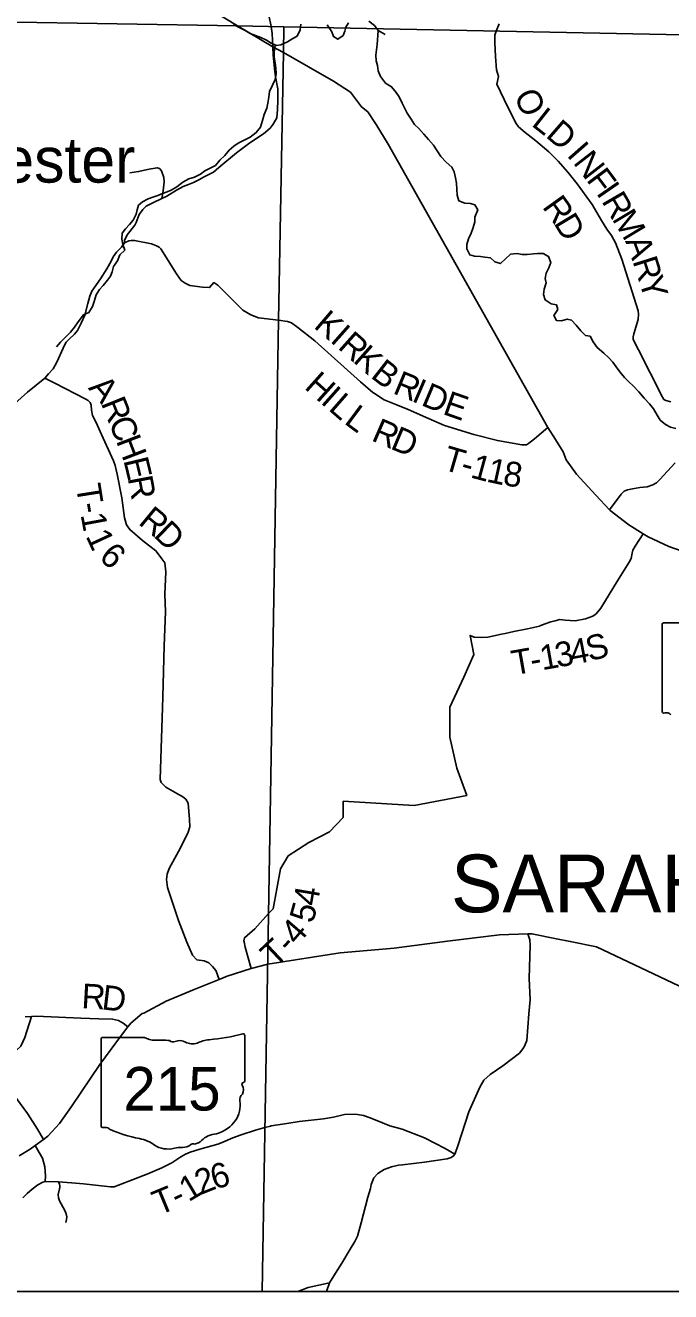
# Model space of a CAD drawing. Extents: x -22 to 431, y -18 to 160.
# Drawn here: x -5.357 to -3.877, y 14.134 to 17.042 of the extents above; entities that cross this region are included whole.
import ezdxf

# ---------------------------------------------------------------- set-up
doc = ezdxf.new("R2010")
doc.units = 0
for name, color, linetype in [('GM_X_Adjacent_County', 7, 'Continuous'), ('GM_X_Adjacent_County_Text', 7, 'Continuous'), ('GM_X_Airport_Location_Class_2', 7, 'Continuous'), ('GM_X_City_Street', 7, 'Continuous'), ('GM_X_City_Street_Text', 7, 'Continuous'), ('GM_X_County_Road', 7, 'Continuous'), ('GM_X_Interstate_Location', 7, 'Continuous'), ('GM_X_Major_River_Text', 7, 'Continuous'), ('GM_X_Minor_River', 7, 'Continuous'), ('GM_X_Minor_River_Text', 7, 'Continuous'), ('GM_X_Rail_Line', 7, 'Continuous'), ('GM_X_Section', 7, 'Continuous')]:
    doc.layers.add(name, color=color, linetype=linetype)

msp = doc.modelspace()

# ---------------------------------------------------------------- linework, layer by layer
at = {"layer": 'GM_X_Adjacent_County_Text'}
for points in [[(-4.7893, 16.9922), (-4.7907, 17.0228), (-4.7931, 17.0387), (-4.7988, 17.0653), (-4.8017, 17.0921), (-4.7983, 17.1237), (-4.7945, 17.1452), (-4.7979, 17.1548)], [(-4.2702, 17.0448), (-4.2773, 17.0283), (-4.2805, 17.0191), (-4.2805, 17.016)], [(-4.2805, 17.016), (-4.2802, 17.0019), (-4.2788, 16.97), (-4.2762, 16.9395), (-4.2721, 16.9238), (-4.276, 16.9062), (-4.2502, 16.854), (-4.2314, 16.8166), (-4.2256, 16.8083), (-4.2103, 16.7955), (-4.1863, 16.7763), (-4.1562, 16.7511), (-4.1351, 16.73), (-4.1126, 16.7043), (-4.0911, 16.6779), (-4.0566, 16.6303), (-4.0355, 16.5933), (-4.0232, 16.5736), (-4.0125, 16.5589), (-4.0033, 16.5422), (-3.989, 16.5051), (-3.9517, 16.3862), (-3.9505, 16.3782), (-3.9512, 16.3665), (-3.9612, 16.3334), (-3.963, 16.3262), (-3.963, 16.3205), (-3.951, 16.2966), (-3.8963, 16.1894)], [(-4.7853, 16.9424), (-4.789, 16.9728), (-4.7893, 16.9922)], [(-5.3813, 16.1734), (-5.3521, 16.1996), (-5.3128, 16.2319), (-5.3037, 16.2414), (-5.2935, 16.2528), (-5.2848, 16.268), (-5.2708, 16.3003), (-5.2667, 16.3086), (-5.2633, 16.3139), (-5.2568, 16.3215), (-5.2447, 16.3329), (-5.2375, 16.3413), (-5.2288, 16.3576), (-5.2205, 16.3762), (-5.2141, 16.4032), (-5.2096, 16.4195), (-5.2047, 16.4312), (-5.185, 16.4593), (-5.1706, 16.4825), (-5.1604, 16.5003), (-5.1555, 16.5102), (-5.1479, 16.5205), (-5.1366, 16.5326), (-5.1298, 16.5425), (-5.1294, 16.5478), (-5.1238, 16.5603), (-5.1064, 16.5827), (-5.1029, 16.5892), (-5.0958, 16.607), (-5.0874, 16.6188), (-5.0803, 16.6268), (-5.0644, 16.634), (-5.0439, 16.6443), (-5.0329, 16.6492), (-5.0106, 16.6629), (-4.9951, 16.6713), (-4.9826, 16.6766), (-4.9713, 16.6808), (-4.9576, 16.688), (-4.9489, 16.6933), (-4.9349, 16.6998), (-4.9258, 16.7044), (-4.9137, 16.715), (-4.8729, 16.7492), (-4.8422, 16.772), (-4.8112, 16.7929), (-4.7957, 16.8054), (-4.7888, 16.8145), (-4.7806, 16.8291), (-4.7787, 16.8482), (-4.7778, 16.8693), (-4.7778, 16.8961), (-4.783, 16.9233), (-4.7853, 16.9424)], [(-3.8963, 16.1894), (-3.8961, 16.1889), (-3.8956, 16.1881), (-3.8922, 16.1828), (-3.888, 16.1801), (-3.8762, 16.1772)], [(-3.8664, 16.0371), (-3.9018, 15.9989), (-3.9097, 15.9913), (-3.9177, 15.9867), (-3.9305, 15.9824), (-3.948, 15.9804), (-3.9642, 15.9776), (-3.9756, 15.9749), (-3.9832, 15.9725), (-3.9907, 15.9656), (-4.017, 15.9293)], [(-5.2301, 14.7627), (-5.3326, 14.7671), (-5.3432, 14.766), (-5.3576, 14.7652)], [(-5.1219, 14.7422), (-5.1326, 14.7507), (-5.1432, 14.7568), (-5.1576, 14.7598), (-5.1887, 14.7609), (-5.2301, 14.7627), (-5.2301, 14.7627)]]:
    msp.add_lwpolyline(points, dxfattribs=at)
at = {"layer": 'GM_X_Airport_Location_Class_2'}
for p, q in [((-3.8933, 15.6699), (-3.7968, 15.6699)), ((-3.8965, 15.6665), (-3.8965, 15.4664)), ((-3.8965, 15.4664), (-3.8965, 15.6665)), ((-3.8965, 15.4664), (-3.8965, 15.6665)), ((-5.1836, 14.7147), (-5.1836, 14.5146)), ((-5.1836, 14.5146), (-5.1836, 14.7147)), ((-5.1836, 14.5146), (-5.1836, 14.7147)), ((-5.1803, 14.7181), (-5.0838, 14.7181)), ((-4.854, 14.7231), (-4.854, 14.6184)), ((-4.854, 14.6184), (-4.854, 14.6184))]:
    msp.add_line(p, q, dxfattribs=at)
for centre, major_axis, start_param, end_param in [((-3.8928, 15.6669), (0.00382, 0), 1.712693, 3.28349), ((-3.8927, 15.4659), (0.00385, 0), 3.00124, 4.508301), ((-3.8921, 15.4864), (0.0294, 0), 4.665946, 4.897461), ((-3.8861, 15.4548), (0.0106, 0), 0.519207, 1.627899), ((-5.1798, 14.7151), (0.00382, 0), 1.712693, 3.28349), ((-5.0608, 14.7414), (0.037, 0), 4.042523, 4.731795), ((-5.0485, 14.6058), (0.133, 0), 1.404758, 1.657858), ((-5.0183, 14.7162), (0.0107, 0), 3.836095, 5.185415), ((-5.0027, 14.693), (0.0222, 0), 0.950623, 2.079405), ((-4.9268, 14.657), (0.0703, 0), 1.699011, 2.107814), ((-4.9714, 14.991), (0.3495, 0), 4.814394, 5.042369), ((-4.8576, 14.7235), (0.00367, 0), 6.141152, 7.989035), ((-4.974, 14.7247), (0.0267, 0), 4.081561, 5.145723), ((-4.8548, 14.6107), (0.00568, 0), 1.883978, 3.671073), ((-4.8909, 14.5975), (0.0341, 0), 5.934695, 6.695948), ((-4.8579, 14.618), (0.00393, 0), 5.05454, 6.418171), ((-4.9518, 14.5613), (0.0874, 0), 5.101752, 6.440018), ((-4.8408, 14.5746), (0.0248, 0), 2.387724, 3.262537), ((-5.1797, 14.5141), (0.00385, 0), 3.00124, 4.508301), ((-5.1792, 14.5346), (0.0294, 0), 4.665946, 4.897461), ((-5.1731, 14.503), (0.0106, 0), 0.519207, 1.627899), ((-5.0393, 14.6828), (0.2524, 0), 4.195997, 4.488961), ((-5.1146, 14.4247), (0.079, 0), 0.823519, 1.323587), ((-4.9756, 14.4952), (0.0282, 0), 4.937069, 5.64225), ((-4.9149, 14.4584), (0.0479, 0), 1.647645, 2.488434), ((-5.0292, 14.502), (0.0501, 0), 4.026481, 4.996735), ((-5.0002, 14.4328), (0.0412, 0), 1.495662, 1.94098), ((-4.9965, 14.487), (0.0267, 0), 4.691044, 5.507374), ((-4.9724, 14.4677), (0.00752, 0), 1.147584, 2.315152)]:
    msp.add_ellipse(centre, major_axis=major_axis, ratio=0.8, start_param=start_param, end_param=end_param, dxfattribs=at)
at = {"layer": 'GM_X_County_Road'}
for points in [[(-5.0416, 15.8138), (-5.0372, 15.8075), (-5.0351, 15.787), (-5.037, 15.7361), (-5.036, 15.6951), (-5.0388, 15.6169), (-5.0417, 15.4989), (-5.0476, 15.3105), (-5.0456, 15.3033), (-5.035, 15.2928), (-5.0027, 15.2745), (-5, 15.273), (-4.9963, 15.2703)], [(-4.6283, 15.2606), (-4.4656, 15.2508), (-4.3446, 15.2737), (-4.3675, 15.3359), (-4.3838, 15.4078), (-4.3838, 15.4765), (-4.3511, 15.5452), (-4.3282, 15.5976), (-4.3369, 15.6412), (-4.3278, 15.6374), (-4.3111, 15.6364), (-4.2963, 15.6373), (-4.2653, 15.6436), (-4.2562, 15.6456)], [(-5.3156, 14.4841), (-5.3295, 14.5079), (-5.3525, 14.5438), (-5.3693, 14.5668), (-5.385, 14.5887), (-5.3954, 14.6099), (-5.4035, 14.6246), (-5.408, 14.6325), (-5.413, 14.639), (-5.4225, 14.6438), (-5.4491, 14.6535), (-5.3778, 14.6886), (-5.3676, 14.6981), (-5.3587, 14.7179), (-5.3432, 14.766)], [(-4.3719, 14.4505), (-4.3938, 14.4631), (-4.4418, 14.4878), (-4.4928, 14.5072), (-4.5209, 14.5154), (-4.5379, 14.5221), (-4.566, 14.5332), (-4.5812, 14.5388), (-4.6002, 14.5417), (-4.6248, 14.5411), (-4.6505, 14.5352), (-4.6736, 14.5309), (-4.7292, 14.5251), (-4.7572, 14.5207), (-4.7933, 14.5148), (-4.7949, 14.5144)], [(-4.7949, 14.5144), (-4.8077, 14.5113), (-4.829, 14.5054), (-4.8618, 14.4945), (-4.8811, 14.4875), (-4.8992, 14.4798), (-4.9093, 14.4755)], [(-4.7322, 14.1345), (-4.7083, 14.144), (-4.6595, 14.155)]]:
    msp.add_lwpolyline(points, dxfattribs=at)
at = {"layer": 'GM_X_Major_River_Text'}
for p, q in [((-4.8708, 17.0405), (-5.7636, 17.0556)), ((-4.7644, 17.0381), (-4.8708, 17.0405)), ((-4.7651, 16.979), (-4.7644, 17.0381)), ((-4.7644, 17.0381), (-2.7601, 16.9978)), ((-4.7761, 16.3648), (-4.7651, 16.979)), ((-4.8141, 14.1345), (-4.7761, 16.3648))]:
    msp.add_line(p, q, dxfattribs=at)
at = {"layer": 'GM_X_Minor_River'}
for points in [[(-4.8796, 17.0432), (-4.8648, 17.0356), (-4.8531, 17.0296), (-4.8417, 17.0232), (-4.8296, 17.0183), (-4.8167, 17.0138), (-4.8042, 17.0078), (-4.7935, 17.001), (-4.781, 16.995), (-4.7708, 16.9965), (-4.7557, 17.0038), (-4.7436, 17.0114), (-4.7334, 17.0168), (-4.7266, 17.0312), (-4.7251, 17.0445)], [(-4.6646, 17.0428), (-4.6543, 17.0269), (-4.6501, 17.0159), (-4.6406, 17.0095), (-4.6278, 17.0186), (-4.6244, 17.0281), (-4.6218, 17.0376), (-4.6161, 17.0471)], [(-4.5692, 17.0511), (-4.5566, 17.0416), (-4.5479, 17.0295), (-4.5319, 17.0202)], [(-4.548, 17.0296), (-4.5493, 17.0072), (-4.5505, 16.9973), (-4.553, 16.9734), (-4.5522, 16.9598), (-4.5496, 16.9492), (-4.5476, 16.937), (-4.5423, 16.9242), (-4.5307, 16.9092)], [(-4.784, 16.9964), (-4.7867, 16.9802), (-4.7863, 16.9692), (-4.7843, 16.9559), (-4.7824, 16.9431), (-4.7816, 16.9302), (-4.7842, 16.9173), (-4.7906, 16.904), (-4.7974, 16.8896), (-4.7989, 16.8767), (-4.8011, 16.8626), (-4.8033, 16.8516), (-4.8093, 16.8368), (-4.8135, 16.8228), (-4.818, 16.808), (-4.8274, 16.7954), (-4.8414, 16.7851), (-4.858, 16.7764), (-4.869, 16.7714), (-4.8788, 16.7642), (-4.8894, 16.755), (-4.8996, 16.7429), (-4.9113, 16.7322), (-4.9211, 16.7197), (-4.9317, 16.7147), (-4.9456, 16.7075), (-4.9555, 16.7002), (-4.9691, 16.693), (-4.9823, 16.6891), (-4.9959, 16.6815), (-5.0095, 16.6712), (-5.0224, 16.6632), (-5.0322, 16.6594), (-5.0424, 16.6552), (-5.053, 16.651), (-5.0651, 16.6471), (-5.0753, 16.6433), (-5.0882, 16.6361), (-5.098, 16.6284), (-5.1006, 16.6178), (-5.1029, 16.6083), (-5.1096, 16.5947), (-5.1183, 16.5844), (-5.1277, 16.5741), (-5.1349, 16.5642), (-5.1356, 16.551), (-5.1337, 16.5381), (-5.1291, 16.5252), (-5.1401, 16.5146), (-5.1461, 16.5009), (-5.1551, 16.488), (-5.1581, 16.4758), (-5.1622, 16.466), (-5.169, 16.4565), (-5.1788, 16.4447), (-5.1868, 16.4348), (-5.1951, 16.4226), (-5.1996, 16.4074), (-5.2033, 16.3964), (-5.2112, 16.3827), (-5.2241, 16.377), (-5.2361, 16.361), (-5.2441, 16.3485), (-5.2535, 16.3371), (-5.2648, 16.3261), (-5.2769, 16.3139), (-5.2859, 16.3032)], [(-4.5307, 16.9092), (-4.5172, 16.9008), (-4.5069, 16.8876), (-4.5, 16.8771), (-4.4926, 16.8628), (-4.4868, 16.8507), (-4.481, 16.8401), (-4.4722, 16.8262), (-4.4648, 16.8141), (-4.4549, 16.8047), (-4.443, 16.792), (-4.4327, 16.7799), (-4.4212, 16.7668), (-4.4123, 16.7532), (-4.4043, 16.7404), (-4.392, 16.7276), (-4.379, 16.716), (-4.3732, 16.7051), (-4.3704, 16.6914), (-4.3684, 16.6789), (-4.3675, 16.6653), (-4.367, 16.652), (-4.3631, 16.6384), (-4.3494, 16.6336), (-4.3361, 16.6326), (-4.3259, 16.6297), (-4.3193, 16.618), (-4.3263, 16.6016), (-4.3259, 16.5906), (-4.3299, 16.5773), (-4.3343, 16.5647), (-4.3406, 16.5518), (-4.3446, 16.5385), (-4.3445, 16.5282), (-4.3376, 16.515), (-4.3266, 16.5117), (-4.3133, 16.5111), (-4.3031, 16.5097), (-4.2898, 16.5075), (-4.2802, 16.4985), (-4.2673, 16.4945), (-4.2557, 16.5056), (-4.2441, 16.516), (-4.2289, 16.5176), (-4.2172, 16.5155), (-4.2058, 16.5152), (-4.1918, 16.5169), (-4.182, 16.5181), (-4.1691, 16.5179), (-4.1569, 16.5112), (-4.1519, 16.4975), (-4.1566, 16.4846), (-4.1626, 16.4728), (-4.1651, 16.4606), (-4.1623, 16.4508), (-4.1671, 16.4363), (-4.1685, 16.4238), (-4.1646, 16.4113), (-4.1512, 16.402), (-4.1391, 16.4002), (-4.136, 16.3892), (-4.1449, 16.3755), (-4.1387, 16.3638), (-4.127, 16.3631), (-4.1142, 16.3671), (-4.1043, 16.3645), (-4.0936, 16.3532), (-4.0832, 16.3404), (-4.0721, 16.3292), (-4.0619, 16.3278), (-4.0546, 16.3153), (-4.0453, 16.3021), (-4.0304, 16.289), (-4.0186, 16.2785), (-4.0098, 16.2684), (-4.0017, 16.2578), (-3.9936, 16.2461), (-3.9829, 16.233), (-3.9729, 16.2232), (-3.9626, 16.2142), (-3.9496, 16.1999), (-3.9377, 16.186), (-3.9255, 16.1725), (-3.9166, 16.1612), (-3.9078, 16.1465), (-3.9012, 16.1355), (-3.889, 16.125), (-3.8776, 16.1191), (-3.8647, 16.1158)]]:
    msp.add_lwpolyline(points, dxfattribs=at)
at = {"layer": 'GM_X_Minor_River_Text'}
for points in [[(-5.0439, 16.6443), (-5.0413, 16.6617), (-5.039, 16.6826), (-5.0394, 16.6924), (-5.0447, 16.7076), (-5.0493, 16.7133), (-5.055, 16.7148), (-5.0731, 16.7113), (-5.0974, 16.706), (-5.1174, 16.7029)], [(-4.5588, 16.1978), (-4.5599, 16.1984), (-4.5881, 16.2232), (-4.6934, 16.317), (-4.7325, 16.3481), (-4.7463, 16.359), (-4.7555, 16.3619), (-4.7761, 16.3648), (-4.8223, 16.3699), (-4.8401, 16.3768), (-4.8585, 16.3878), (-4.9155, 16.4453), (-4.9247, 16.4511), (-4.9347, 16.4394), (-4.9506, 16.4406), (-4.9799, 16.4446), (-4.9905, 16.4494), (-5.0001, 16.456), (-5.0106, 16.4714), (-5.0464, 16.5284), (-5.0499, 16.5322), (-5.056, 16.5355), (-5.0679, 16.5398), (-5.1066, 16.5478), (-5.1142, 16.5477), (-5.1195, 16.5468), (-5.1298, 16.5425)], [(-5.3128, 16.2319), (-5.2892, 16.2198), (-5.2182, 16.1836), (-5.2132, 16.1802), (-5.2087, 16.1757), (-5.206, 16.1697), (-5.2051, 16.1579), (-5.2028, 16.1458), (-5.1947, 16.1299), (-5.1828, 16.1023), (-5.1551, 16.0422), (-5.1512, 16.0312), (-5.1469, 16.0115), (-5.1355, 15.9566), (-5.1299, 15.9107), (-5.1249, 15.8948), (-5.1176, 15.8839), (-5.0883, 15.8587), (-5.0578, 15.8354), (-5.0456, 15.8195), (-5.0438, 15.8169), (-5.0416, 15.8138)], [(-4.1588, 16.1186), (-4.1893, 16.0922), (-4.2032, 16.0815), (-4.2074, 16.0784), (-4.2184, 16.0787), (-4.2742, 16.0882), (-4.3286, 16.1026), (-4.3959, 16.1227), (-4.4327, 16.1392), (-4.4787, 16.1593), (-4.5075, 16.1708), (-4.534, 16.1817), (-4.5588, 16.1978)], [(-4.1769, 15.6629), (-4.1645, 15.6674), (-4.1517, 15.6721), (-4.1418, 15.6748), (-4.1308, 15.6772), (-4.1191, 15.6761), (-4.0959, 15.6748), (-4.0721, 15.6791), (-4.0554, 15.6853), (-4.0479, 15.6903), (-4.0373, 15.7037), (-3.9991, 15.7666), (-3.9721, 15.8089), (-3.9676, 15.8173), (-3.9651, 15.8299), (-3.9636, 15.8371), (-3.9583, 15.8463), (-3.9402, 15.8745)], [(-4.2562, 15.6456), (-4.2369, 15.6499), (-4.2054, 15.6565), (-4.1781, 15.6624), (-4.1769, 15.6629)], [(-4.9963, 15.2703), (-4.9893, 15.2651), (-4.9836, 15.2556), (-4.9803, 15.2188), (-4.9801, 15.2017), (-4.9838, 15.1896), (-4.9935, 15.1686), (-5.0062, 15.1446), (-5.0272, 15.1057), (-5.0316, 15.0932), (-5.0334, 15.081), (-5.0314, 15.0624), (-5.0062, 14.9863), (-4.9869, 14.9371), (-4.9735, 14.9073), (-4.9635, 14.896), (-4.9468, 14.8941), (-4.9361, 14.889), (-4.9277, 14.8812), (-4.9192, 14.8708), (-4.9191, 14.8706)], [(-4.7941, 15.0081), (-4.7885, 15.0137), (-4.7722, 15.1053), (-4.7542, 15.1347), (-4.7068, 15.1658), (-4.6593, 15.1903), (-4.6283, 15.223), (-4.6283, 15.2606)], [(-4.8556, 14.9378), (-4.856, 14.9399), (-4.8542, 14.9468), (-4.8306, 14.9672), (-4.7993, 15.0029), (-4.7941, 15.0081)], [(-4.2021, 14.7725), (-4.1995, 14.8043), (-4.2013, 14.8532), (-4.1989, 14.93), (-4.2001, 14.9425), (-4.2044, 14.9559)], [(-4.8391, 14.8765), (-4.8526, 14.9252), (-4.8556, 14.9378)], [(-4.9191, 14.8706), (-4.9123, 14.8513)], [(-4.666, 14.1345), (-4.6595, 14.155), (-4.6494, 14.171), (-4.6314, 14.2), (-4.612, 14.232), (-4.6011, 14.2499), (-4.5951, 14.2617), (-4.587, 14.2922), (-4.5716, 14.3515), (-4.5656, 14.3712), (-4.5638, 14.3807), (-4.5575, 14.396), (-4.5485, 14.4059), (-4.5338, 14.4147), (-4.5172, 14.4209), (-4.5009, 14.4245), (-4.4922, 14.4255), (-4.4418, 14.432), (-4.3895, 14.4392), (-4.3804, 14.4423), (-4.3747, 14.4461), (-4.3719, 14.4505), (-4.371, 14.4518), (-4.3647, 14.4712), (-4.3398, 14.547), (-4.3148, 14.6037), (-4.3058, 14.6197), (-4.2908, 14.6331), (-4.2621, 14.6531), (-4.224, 14.6818), (-4.2161, 14.6917), (-4.212, 14.6982), (-4.2071, 14.7112), (-4.2021, 14.7723), (-4.2021, 14.7725)], [(-5.3116, 14.3874), (-5.311, 14.4003), (-5.3126, 14.4212), (-5.3181, 14.4409), (-5.3257, 14.4541), (-5.3349, 14.4698)], [(-4.9093, 14.4755), (-4.9155, 14.4728), (-4.9566, 14.4619), (-4.9789, 14.4549), (-4.9895, 14.4499), (-5.0008, 14.4441), (-5.0215, 14.4303), (-5.0442, 14.4187), (-5.0759, 14.4048), (-5.1533, 14.3754), (-5.162, 14.3753), (-5.2241, 14.382), (-5.2511, 14.3843), (-5.2512, 14.3844)], [(-5.2512, 14.3844), (-5.281, 14.3869), (-5.3116, 14.3874), (-5.3173, 14.3855), (-5.3286, 14.3797), (-5.3414, 14.3701), (-5.3527, 14.3602), (-5.3632, 14.3498)], [(-5.2642, 14.2931), (-5.2626, 14.2998), (-5.2623, 14.3063), (-5.2637, 14.3134), (-5.2664, 14.3211), (-5.2792, 14.3433), (-5.2814, 14.3501), (-5.2817, 14.3578), (-5.2788, 14.3708), (-5.2784, 14.374), (-5.2784, 14.3777), (-5.2789, 14.381), (-5.281, 14.3869)]]:
    msp.add_lwpolyline(points, dxfattribs=at)
at = {"layer": 'GM_X_Rail_Line'}
for points in [[(-4.9327, 17.0778), (-4.8708, 17.0405), (-4.7893, 16.9922), (-4.7651, 16.979), (-4.6506, 16.9138), (-4.6114, 16.8884), (-4.5858, 16.8545), (-4.5717, 16.8428), (-4.5522, 16.814), (-4.5251, 16.769), (-4.1588, 16.1186), (-4.1409, 16.0906), (-4.1238, 16.0627), (-4.1169, 16.0445), (-4.093, 16.0112), (-4.0486, 15.9632), (-4.017, 15.9293), (-4.0158, 15.928), (-3.9732, 15.8952), (-3.9402, 15.8745), (-3.9282, 15.867), (-3.8813, 15.8449), (-3.787, 15.8126)], [(-5.3713, 14.4465), (-5.3463, 14.4613), (-5.3349, 14.4698), (-5.3156, 14.4841), (-5.3058, 14.4914), (-5.2789, 14.5206), (-5.251, 14.5599), (-5.1861, 14.656), (-5.1368, 14.723), (-5.1219, 14.7422), (-5.1152, 14.7508), (-5.0895, 14.7728), (-5.0857, 14.7738), (-5.0338, 14.8014), (-4.9698, 14.8278), (-4.9123, 14.8513), (-4.8941, 14.8589), (-4.8391, 14.8765), (-4.8013, 14.8862), (-4.6351, 14.9124), (-4.511, 14.9232), (-4.3886, 14.9393), (-4.2695, 14.9538), (-4.2044, 14.9559), (-4.1953, 14.9562), (-4.1389, 14.9441), (-4.1071, 14.9386), (-4.0467, 14.9261), (-3.7999, 14.8091)]]:
    msp.add_lwpolyline(points, dxfattribs=at)
at = {"layer": 'GM_X_Section'}
msp.add_line((-1.9192, 14.1345), (-8.7192, 14.1345), dxfattribs=at)

# ---------------------------------------------------------------- texts
at = {"layer": 'GM_X_Adjacent_County'}
msp.add_text('Rochester', height=0.10417, rotation=0, dxfattribs=at).set_placement((-5.7397, 16.6806))
at = {"layer": 'GM_X_Airport_Location_Class_2'}
msp.add_text('215', height=0.1, dxfattribs=at).set_placement((-5.1324, 14.5503))
at = {"layer": 'GM_X_City_Street'}
for s, rotation, p in [('O', 295.5501, (-4.2377, 16.8798)), ('L', 321.8164, (-4.1985, 16.8126)), ('D', 318.9416, (-4.1657, 16.7869)), ('I', 311.3269, (-4.1171, 16.743)), ('N', 307.8076, (-4.1023, 16.7261)), ('F', 306.8214, (-4.0718, 16.6868)), ('I', 304.7401, (-4.0492, 16.6566)), ('R', 300.1665, (-4.0365, 16.6384)), ('R', 305.6606, (-4.173, 16.6248)), ('D', 301.1705, (-4.1465, 16.5879)), ('M', 301.1074, (-4.0126, 16.5972)), ('A', 290.1723, (-3.9819, 16.547)), ('R', 287.6462, (-3.9649, 16.5007)), ('Y', 287.3682, (-3.9508, 16.4563)), ('R', 356.6963, (-5.2294, 14.7854)), ('D', 353.3223, (-5.1837, 14.7828))]:
    msp.add_text(s, height=0.0568, rotation=rotation, dxfattribs=at).set_placement(p)
at = {"layer": 'GM_X_City_Street_Text'}
for s, rotation, p in [('K', 319.471, (-4.698, 16.3491)), ('I', 318.4631, (-4.6602, 16.3168)), ('R', 318.3717, (-4.6427, 16.3013)), ('K', 318.4299, (-4.6078, 16.2703)), ('B', 322.0612, (-4.5674, 16.2346)), ('A', 310.5677, (-5.2145, 16.2083)), ('H', 318.286, (-4.7194, 16.2091)), ('R', 337.4897, (-4.5165, 16.1977)), ('I', 336.8301, (-4.4735, 16.1799)), ('I', 318.405, (-4.682, 16.1757)), ('L', 318.9688, (-4.6641, 16.1598)), ('D', 337.2511, (-4.4517, 16.1705)), ('E', 340.5943, (-4.4022, 16.1499)), ('R', 291.9942, (-5.1845, 16.1745)), ('L', 323.4194, (-4.6282, 16.1289)), ('C', 291.7384, (-5.167, 16.1313)), ('R', 336.6099, (-4.5658, 16.0894)), ('D', 337.3312, (-4.5223, 16.0705)), ('H', 290.9978, (-5.1498, 16.0881)), ('T', 343.795, (-4.4028, 16.0228)), ('E', 283.5134, (-5.1325, 16.0433)), ('1', 344.8453, (-4.3385, 16.0042)), ('-', 343.998, (-4.3618, 16.0109)), ('1', 347.8662, (-4.3015, 15.9943)), ('8', 351.6416, (-4.2633, 15.9862)), ('T', 278.972, (-5.2414, 15.9851)), ('R', 280.7136, (-5.1227, 16.0027)), ('-', 279.2084, (-5.2347, 15.9429)), ('R', 320.5197, (-5.1002, 15.898)), ('1', 280.5375, (-5.2307, 15.9184)), ('D', 315.6182, (-5.0652, 15.8692)), ('1', 294.8043, (-5.2196, 15.8694)), ('6', 317.4092, (-5.1907, 15.818)), ('S', 15.0531, (-4.0632, 15.5811)), ('T', 10.0499, (-4.2366, 15.5494)), ('1', 10.0904, (-4.1717, 15.5609)), ('3', 10.264, (-4.1371, 15.5671)), ('4', 10.8818, (-4.102, 15.5735)), ('-', 10.0538, (-4.1947, 15.5569)), ('4', 80.2875, (-4.6872, 15.0177)), ('5', 74.7182, (-4.6977, 14.978)), ('4', 49.1551, (-4.7335, 14.9274)), ('T', 43.2239, (-4.7846, 14.8764)), ('-', 47.4918, (-4.7504, 14.9088)), ('2', 21.6719, (-4.9549, 14.3563)), ('6', 15.2127, (-4.924, 14.3686)), ('1', 30.6248, (-4.9829, 14.3395)), ('T', 22.5177, (-5.0509, 14.3089)), ('-', 26.2582, (-5.008, 14.3269))]:
    msp.add_text(s, height=0.0568, rotation=rotation, dxfattribs=at).set_placement(p)
at = {"layer": 'GM_X_Interstate_Location'}
msp.add_text('SARAHSVILLE', height=0.132576, rotation=0, dxfattribs=at).set_placement((-4.3809, 15.0053))

doc.saveas('drawing.dxf')
